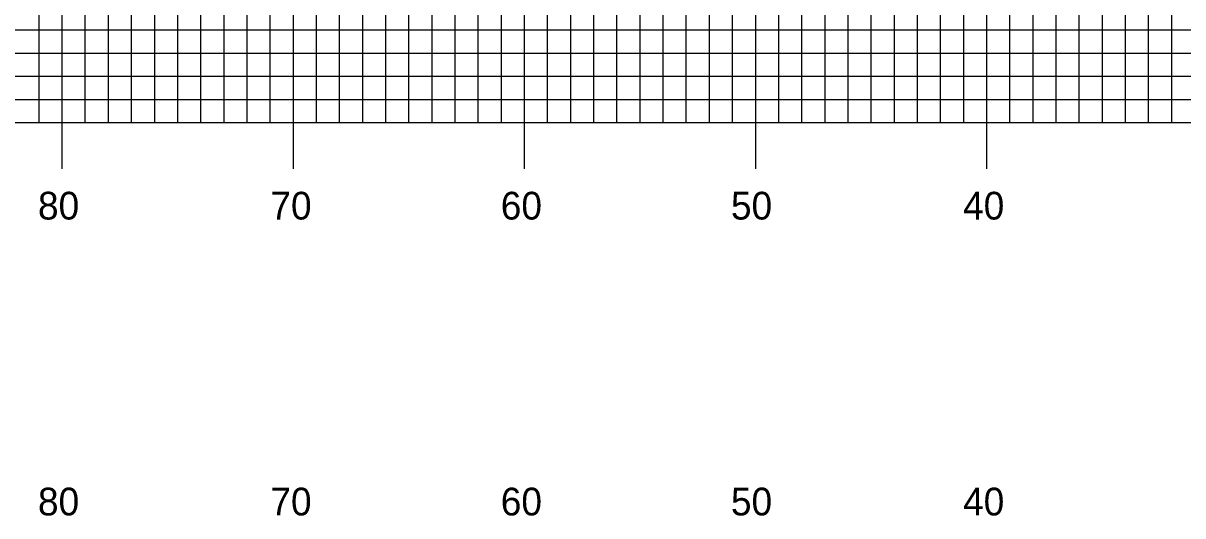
# Model space of a CAD drawing. Extents: x 1789337 to 1789680, y 442591 to 442811.
# Drawn here: x 1789421 to 1789471.1, y 442651.6 to 442673 of the extents above; entities that cross this region are included whole.
import ezdxf

# ---------------------------------------------------------------- set-up
doc = ezdxf.new("R2010")
doc.units = 0
for name, color, linetype in [('H_V ANNOTATION', 7, 'Continuous'), ('MAJOR', 7, 'Continuous'), ('MINOR', 7, 'Continuous')]:
    doc.layers.add(name, color=color, linetype=linetype)

msp = doc.modelspace()

# ---------------------------------------------------------------- linework, layer by layer
at = {"layer": 'MAJOR'}
for p, q in [((1789422.67, 442668.665), (1789422.67, 442703.665)), ((1789432.67, 442668.665), (1789432.67, 442703.665)), ((1789442.67, 442668.665), (1789442.67, 442703.665)), ((1789452.67, 442668.665), (1789452.67, 442703.665)), ((1789462.67, 442668.665), (1789462.67, 442703.665)), ((1789362.67, 442668.665), (1789642.67, 442668.665)), ((1789362.67, 442668.665), (1789642.67, 442668.665)), ((1789422.67, 442666.661), (1789422.67, 442668.665)), ((1789432.67, 442666.661), (1789432.67, 442668.665)), ((1789442.67, 442666.661), (1789442.67, 442668.665)), ((1789452.67, 442666.661), (1789452.67, 442668.665)), ((1789462.67, 442666.661), (1789462.67, 442668.665))]:
    msp.add_line(p, q, dxfattribs=at)
at = {"layer": 'MINOR'}
for p, q in [((1789421.67, 442668.665), (1789421.67, 442703.665)), ((1789423.67, 442668.665), (1789423.67, 442703.665)), ((1789424.67, 442668.665), (1789424.67, 442703.665)), ((1789425.67, 442668.665), (1789425.67, 442703.665)), ((1789426.67, 442668.665), (1789426.67, 442703.665)), ((1789427.67, 442668.665), (1789427.67, 442703.665)), ((1789428.67, 442668.665), (1789428.67, 442703.665)), ((1789429.67, 442668.665), (1789429.67, 442703.665)), ((1789430.67, 442668.665), (1789430.67, 442703.665)), ((1789431.67, 442668.665), (1789431.67, 442703.665)), ((1789433.67, 442668.665), (1789433.67, 442703.665)), ((1789434.67, 442668.665), (1789434.67, 442703.665)), ((1789435.67, 442668.665), (1789435.67, 442703.665)), ((1789436.67, 442668.665), (1789436.67, 442703.665)), ((1789437.67, 442668.665), (1789437.67, 442703.665)), ((1789438.67, 442668.665), (1789438.67, 442703.665)), ((1789439.67, 442668.665), (1789439.67, 442703.665)), ((1789440.67, 442668.665), (1789440.67, 442703.665)), ((1789441.67, 442668.665), (1789441.67, 442703.665)), ((1789443.67, 442668.665), (1789443.67, 442703.665)), ((1789444.67, 442668.665), (1789444.67, 442703.665)), ((1789445.67, 442668.665), (1789445.67, 442703.665)), ((1789446.67, 442668.665), (1789446.67, 442703.665)), ((1789447.67, 442668.665), (1789447.67, 442703.665)), ((1789448.67, 442668.665), (1789448.67, 442703.665)), ((1789449.67, 442668.665), (1789449.67, 442703.665)), ((1789450.67, 442668.665), (1789450.67, 442703.665)), ((1789451.67, 442668.665), (1789451.67, 442703.665)), ((1789453.67, 442668.665), (1789453.67, 442703.665)), ((1789454.67, 442668.665), (1789454.67, 442703.665)), ((1789455.67, 442668.665), (1789455.67, 442703.665)), ((1789456.67, 442668.665), (1789456.67, 442703.665)), ((1789457.67, 442668.665), (1789457.67, 442703.665)), ((1789458.67, 442668.665), (1789458.67, 442703.665)), ((1789459.67, 442668.665), (1789459.67, 442703.665)), ((1789460.67, 442668.665), (1789460.67, 442703.665)), ((1789461.67, 442668.665), (1789461.67, 442703.665)), ((1789463.67, 442668.665), (1789463.67, 442703.665)), ((1789464.67, 442668.665), (1789464.67, 442703.665)), ((1789465.67, 442668.665), (1789465.67, 442703.665)), ((1789466.67, 442668.665), (1789466.67, 442703.665)), ((1789467.67, 442668.665), (1789467.67, 442703.665)), ((1789468.67, 442668.665), (1789468.67, 442703.665)), ((1789469.67, 442668.665), (1789469.67, 442703.665)), ((1789470.67, 442668.665), (1789470.67, 442703.665)), ((1789362.67, 442672.665), (1789642.67, 442672.665)), ((1789362.67, 442671.665), (1789642.67, 442671.665)), ((1789362.67, 442670.665), (1789642.67, 442670.665)), ((1789362.67, 442669.665), (1789642.67, 442669.665))]:
    msp.add_line(p, q, dxfattribs=at)

# ---------------------------------------------------------------- texts
at = {"layer": 'H_V ANNOTATION'}
for s, p in [('80', (1789421.62, 442664.465)), ('70', (1789431.674, 442664.465)), ('60', (1789441.642, 442664.465)), ('50', (1789451.599, 442664.465)), ('40', (1789461.642, 442664.465)), ('80', (1789421.62, 442651.665)), ('70', (1789431.674, 442651.665)), ('60', (1789441.642, 442651.665)), ('50', (1789451.599, 442651.665)), ('40', (1789461.642, 442651.665))]:
    msp.add_text(s, height=1.2, dxfattribs=at).set_placement(p)

doc.saveas('drawing.dxf')
